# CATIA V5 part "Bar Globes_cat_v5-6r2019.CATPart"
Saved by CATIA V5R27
Part number: Bar Globes
Bounding box of the stored display mesh (mm): x -5.986 to 5.986, y -4.926 to 5, z -5.986 to 5.986
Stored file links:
  E:\_Deepak\2017_Deepak\CATIA\Resources\Tutorial Files\Tutorials\c16_catia_v5_6r2016_tut\Bench vice\Bar Globes_cat_v5-6r2016.CATPart
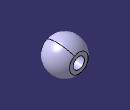
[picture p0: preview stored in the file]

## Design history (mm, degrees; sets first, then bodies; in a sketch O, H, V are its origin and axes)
Body1 (main body)
  Sketch1 on yz-plane, origin (0, 0, 0), H (0, 1, 0), V (0, 0, 1)
    arc A1 centre (0, 0) radius 6 from (6, 0) to (-6, 0) ccw
    line L1 (-6, 0) -> (6, 0)
    radius A1 = 6
    horizontal: L1 H
    coincidence: H L1
  Shaft1: profile Sketch1, axis edge of Sketch1, angle 360
  Sketch2 on yz-plane, origin (0, 0, 0), H (0, 1, 0), V (0, 0, 1)
    line L1 (-5, 7.2498) -> (5, 7.2498)
    line L2 (5, 7.2498) -> (5, -8.5554)
    line L3 (5, -8.5554) -> (1.27, -8.5554)
    line L4 (-5, -8.5554) -> (-5, 7.2498)
    line L5 (1.27, -8.5554) -> (1.27, -9.941)
    line L6 (1.27, -9.941) -> (8.2768, -9.941)
    line L7 (8.2768, -9.941) -> (8.2768, 9.8096)
    line L8 (8.2768, 9.8096) -> (-8.9775, 9.8096)
    line L9 (-8.9775, 9.8096) -> (-8.9775, -10.3789)
    line L10 (-8.9775, -10.3789) -> (-2.0145, -10.3789)
    line L11 (-2.0145, -10.3789) -> (-2.0145, -8.5554)
    point P12 (-2.0145, -8.5554)
    line L12 (-2.0145, -8.5554) -> (-5, -8.5554)
    length L1 = 10
    distance V L4 = 5
    horizontal: L1 H, L3 H, L6 H, L8 H, L10 H, L12 H
    vertical: L2 V, L4 V, L5 V, L7 V, L9 V, L11 V
    coincidence: P12 L3, L3 L12
  Pocket1: profile Sketch2, direction (-1, 0, 0), length 20, mirrored extent
  Sketch3 on face of Pocket1, origin (0.8583, -5, 1.5686), H (1, 0, 0), V (0, 0, 1)
    point P1 (-0.8583, -1.5686)
    reference intersected line E1 through (0, -1.5686) direction (-1, 0) from xy-plane
    reference intersected line E2 through (-0.8583, 0) direction (0, 1) from yz-plane
    coincidence: P1 E1, E2 P1
  Hole1: placed by Sketch3, at (0, -5, 0) direction (0, 1, 0), diameter 4, depth 10, countersink depth 1.5, countersink angle 90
